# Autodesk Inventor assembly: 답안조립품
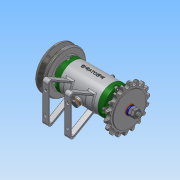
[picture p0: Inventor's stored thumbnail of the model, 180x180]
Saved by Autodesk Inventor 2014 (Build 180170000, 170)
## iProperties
Created: 2016-03
Part Number: 답안조립품
Document SubType Name: Assembly
Designer: SCD-A12
Author: SCD-A12
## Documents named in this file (16)
- C:\Users\SCD-A12\Desktop\460307V1003\답안조립품.iam
- C:\Users\SCD-A12\Desktop\460307V1003\V벨트풀리.ipt
- C:\Users\SCD-A12\Desktop\460307V1003\너트 M 8.ipt
- C:\Users\SCD-A12\Desktop\460307V1003\니플 M 6 x 0.75.ipt
- C:\Users\SCD-A12\Desktop\460307V1003\베어링 15 x 32 x 9.ipt
- C:\Users\SCD-A12\Desktop\460307V1003\본체.ipt
- C:\Users\SCD-A12\Desktop\460307V1003\볼트 M 6 x 8.ipt
- C:\Users\SCD-A12\Desktop\460307V1003\볼트 M4 x 12.ipt
- C:\Users\SCD-A12\Desktop\460307V1003\스프로킷.ipt
- C:\Users\SCD-A12\Desktop\460307V1003\스프링와셔 8.ipt
- C:\Users\SCD-A12\Desktop\460307V1003\오일 실 15 25 7.ipt
- C:\Users\SCD-A12\Desktop\460307V1003\와셔 6x11.5.ipt
- C:\Users\SCD-A12\Desktop\460307V1003\와셔 8x17.ipt
- C:\Users\SCD-A12\Desktop\460307V1003\축.ipt
- C:\Users\SCD-A12\Desktop\460307V1003\커버.ipt
- C:\Users\SCD-A12\Desktop\460307V1003\키 3 x 3 x 12.ipt
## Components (11 placed, 3 different names)
1. V벨트풀리:1
2. KS B 2023 6002 - 15 x 32 x 9:1
3. ISO 4762 M4 x 12:1
4. KS B 2023 6002 - 15 x 32 x 9:2
5. ISO 4762 M4 x 12:2
6. ISO 4762 M4 x 12:3
7. ISO 4762 M4 x 12:4
8. ISO 4762 M4 x 12:5
9. ISO 4762 M4 x 12:6
10. ISO 4762 M4 x 12:7
11. ISO 4762 M4 x 12:8
